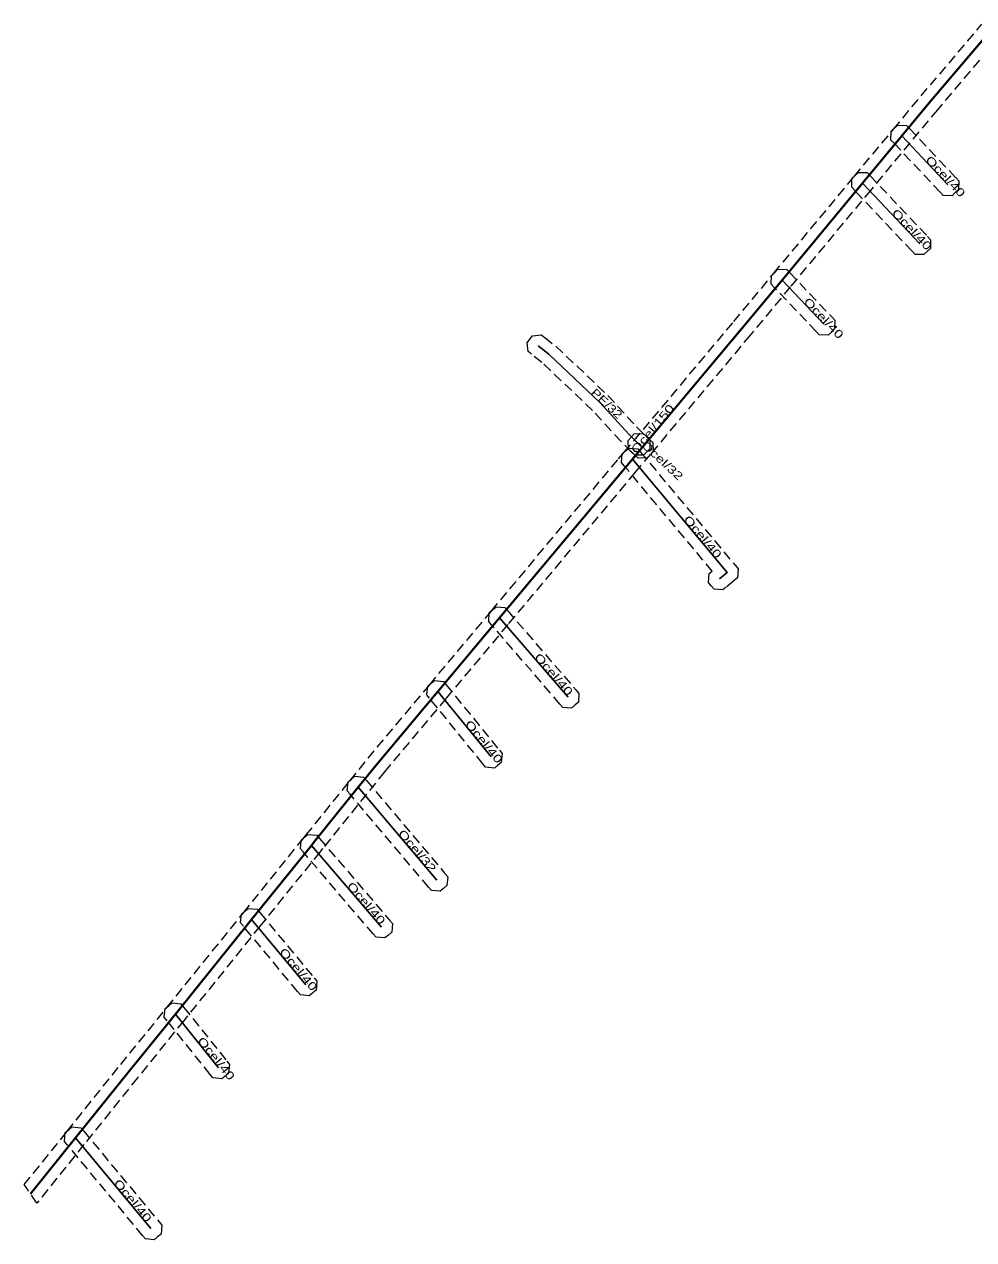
# Model space of a CAD drawing. Extents: x -588392 to -586332, y -1208963 to -1206334.
# Drawn here: x -588392.3 to -588303.3, y -1206538.6 to -1206424.7 of the extents above; entities that cross this region are included whole.
import ezdxf

# ---------------------------------------------------------------- set-up
doc = ezdxf.new("R2010")
doc.units = 0
doc.header["$LTSCALE"] = 0.3
doc.linetypes.add('MEDIUM_DASHED', pattern=[4.5, 3, -1.5])
doc.layers.add('1', color=7, linetype='MEDIUM_DASHED', lineweight=13)
doc.layers.add('24', color=7, linetype='Continuous', lineweight=25)
doc.layers.add('30', color=7, linetype='Continuous')

msp = doc.modelspace()

# ---------------------------------------------------------------- linework, layer by layer
at = {"layer": '1'}
msp.add_lwpolyline([(-588301.028, -1206425.988), (-588306.724, -1206432.693), (-588309.29, -1206435.789), (-588312.971, -1206440.219), (-588320.511, -1206449.299), (-588324.272, -1206453.831), (-588333.617, -1206464.978), (-588334.537, -1206466.076), (-588335.066, -1206466.696), (-588346.983, -1206480.942), (-588352.773, -1206487.852), (-588358.537, -1206494.735), (-588360.215, -1206496.814), (-588364.342, -1206501.928), (-588364.606, -1206502.255), (-588370.212, -1206509.198), (-588377.362, -1206518.059), (-588381.692, -1206523.408), (-588386.721, -1206529.667), (-588391.139, -1206535.159), (-588392.299, -1206533.411), (-588388.279, -1206528.413), (-588383.248, -1206522.152), (-588378.918, -1206516.801), (-588371.768, -1206507.942), (-588366.162, -1206500.999), (-588365.898, -1206500.672), (-588361.771, -1206495.558), (-588360.083, -1206493.465), (-588354.307, -1206486.568), (-588348.517, -1206479.658), (-588336.594, -1206465.404), (-588336.063, -1206464.784), (-588335.149, -1206463.694), (-588325.808, -1206452.549), (-588322.049, -1206448.021), (-588314.509, -1206438.941), (-588310.83, -1206434.511), (-588308.256, -1206431.407), (-588302.552, -1206424.692)], dxfattribs=at)
for points in [[(-588309.617, -1206434.162), (-588309.333, -1206434.464), (-588305.003, -1206439.054), (-588304.718, -1206439.355), (-588304.742, -1206440.183), (-588305.044, -1206440.467), (-588305.345, -1206440.752), (-588306.173, -1206440.728), (-588306.457, -1206440.426), (-588310.787, -1206435.836), (-588311.072, -1206435.535), (-588311.048, -1206434.707), (-588310.746, -1206434.423), (-588310.445, -1206434.138)], [(-588313.298, -1206438.592), (-588313.013, -1206438.893), (-588307.643, -1206444.573), (-588307.358, -1206444.874), (-588307.382, -1206445.702), (-588307.683, -1206445.987), (-588307.984, -1206446.272), (-588308.812, -1206446.248), (-588309.097, -1206445.947), (-588314.467, -1206440.267), (-588314.752, -1206439.966), (-588314.728, -1206439.138), (-588314.427, -1206438.853), (-588314.126, -1206438.568)], [(-588320.84, -1206447.671), (-588320.555, -1206447.972), (-588316.625, -1206452.112), (-588316.34, -1206452.412), (-588316.361, -1206453.24), (-588316.662, -1206453.525), (-588316.962, -1206453.81), (-588317.79, -1206453.789), (-588318.075, -1206453.488), (-588322.005, -1206449.348), (-588322.29, -1206449.048), (-588322.269, -1206448.22), (-588321.968, -1206447.935), (-588321.668, -1206447.65)], [(-588335.094, -1206465.06), (-588335.387, -1206464.767), (-588336.373, -1206463.781), (-588339.034, -1206460.872), (-588343.795, -1206456.367), (-588344.76, -1206455.605), (-588345.085, -1206455.348), (-588345.182, -1206454.525), (-588344.925, -1206454.2), (-588344.668, -1206453.875), (-588343.845, -1206453.778), (-588343.52, -1206454.035), (-588342.485, -1206454.853), (-588337.606, -1206459.468), (-588334.927, -1206462.399), (-588333.973, -1206463.353), (-588333.68, -1206463.646), (-588333.68, -1206464.474), (-588333.973, -1206464.767), (-588334.266, -1206465.06)], [(-588334.76, -1206465.351), (-588335.064, -1206465.069), (-588335.361, -1206464.793), (-588335.664, -1206464.511), (-588335.695, -1206463.683), (-588335.413, -1206463.379), (-588335.131, -1206463.076), (-588334.303, -1206463.045), (-588333.999, -1206463.327), (-588333.702, -1206463.603), (-588333.399, -1206463.885), (-588333.368, -1206464.713), (-588333.65, -1206465.017), (-588333.932, -1206465.32)], [(-588328.109, -1206476.159), (-588327.828, -1206475.924), (-588336.067, -1206466.071), (-588336.333, -1206465.753), (-588336.259, -1206464.929), (-588335.941, -1206464.663), (-588335.623, -1206464.397), (-588334.799, -1206464.471), (-588334.533, -1206464.789), (-588325.653, -1206475.409), (-588325.387, -1206475.726), (-588325.424, -1206476.139), (-588325.461, -1206476.552), (-588325.779, -1206476.817), (-588326.509, -1206477.427), (-588326.827, -1206477.693), (-588327.651, -1206477.619), (-588327.917, -1206477.301), (-588328.183, -1206476.983)], [(-588347.263, -1206479.333), (-588346.993, -1206479.647), (-588340.583, -1206487.077), (-588340.313, -1206487.391), (-588340.373, -1206488.217), (-588340.687, -1206488.487), (-588341.001, -1206488.757), (-588341.827, -1206488.697), (-588342.097, -1206488.383), (-588348.507, -1206480.953), (-588348.777, -1206480.639), (-588348.717, -1206479.813), (-588348.403, -1206479.543), (-588348.089, -1206479.273)], [(-588353.026, -1206486.258), (-588352.764, -1206486.579), (-588347.774, -1206492.709), (-588347.513, -1206493.03), (-588347.598, -1206493.854), (-588347.919, -1206494.116), (-588348.24, -1206494.377), (-588349.064, -1206494.292), (-588349.326, -1206493.971), (-588354.316, -1206487.841), (-588354.577, -1206487.52), (-588354.492, -1206486.696), (-588354.171, -1206486.434), (-588353.85, -1206486.173)], [(-588354.147, -1206505.858), (-588354.414, -1206505.542), (-588361.758, -1206496.831), (-588362.025, -1206496.514), (-588361.954, -1206495.688), (-588361.638, -1206495.421), (-588361.321, -1206495.154), (-588360.495, -1206495.225), (-588360.228, -1206495.541), (-588352.884, -1206504.252), (-588352.617, -1206504.569), (-588352.688, -1206505.395), (-588353.004, -1206505.662), (-588353.321, -1206505.929)], [(-588364.894, -1206500.662), (-588364.625, -1206500.976), (-588358.072, -1206508.625), (-588357.802, -1206508.94), (-588357.866, -1206509.766), (-588358.18, -1206510.035), (-588358.495, -1206510.305), (-588359.321, -1206510.241), (-588359.59, -1206509.927), (-588366.143, -1206502.278), (-588366.413, -1206501.963), (-588366.349, -1206501.137), (-588366.035, -1206500.868), (-588365.72, -1206500.598)], [(-588370.486, -1206507.612), (-588370.221, -1206507.931), (-588365.141, -1206514.041), (-588364.876, -1206514.36), (-588364.952, -1206515.184), (-588365.271, -1206515.449), (-588365.59, -1206515.714), (-588366.414, -1206515.638), (-588366.679, -1206515.319), (-588371.759, -1206509.209), (-588372.024, -1206508.89), (-588371.948, -1206508.066), (-588371.629, -1206507.801), (-588371.31, -1206507.536)], [(-588377.62, -1206516.481), (-588377.36, -1206516.804), (-588373.32, -1206521.834), (-588373.061, -1206522.157), (-588373.151, -1206522.98), (-588373.474, -1206523.24), (-588373.797, -1206523.499), (-588374.62, -1206523.409), (-588374.88, -1206523.086), (-588378.92, -1206518.056), (-588379.179, -1206517.733), (-588379.089, -1206516.91), (-588378.766, -1206516.65), (-588378.443, -1206516.391)], [(-588386.996, -1206528.082), (-588386.731, -1206528.401), (-588379.671, -1206536.901), (-588379.406, -1206537.22), (-588379.482, -1206538.044), (-588379.801, -1206538.309), (-588380.12, -1206538.574), (-588380.944, -1206538.498), (-588381.209, -1206538.179), (-588388.269, -1206529.679), (-588388.534, -1206529.36), (-588388.458, -1206528.536), (-588388.139, -1206528.271), (-588387.82, -1206528.006)]]:
    msp.add_lwpolyline(points, close=True, dxfattribs=at)
at = {"layer": '24'}
for p, q in [((-588310.06, -1206435.15), (-588305.73, -1206439.74)), ((-588313.74, -1206439.58), (-588308.37, -1206445.26)), ((-588321.28, -1206448.66), (-588317.35, -1206452.8)), ((-588334.383, -1206464.336), (-588334.68, -1206464.06)), ((-588347.75, -1206480.3), (-588341.34, -1206487.73)), ((-588353.54, -1206487.21), (-588348.55, -1206493.34)), ((-588353.649, -1206504.897), (-588360.993, -1206496.186)), ((-588365.384, -1206501.627), (-588358.831, -1206509.276)), ((-588370.99, -1206508.57), (-588365.91, -1206514.68)), ((-588378.14, -1206517.43), (-588374.1, -1206522.46)), ((-588387.5, -1206529.04), (-588380.44, -1206537.54))]:
    msp.add_line(p, q, dxfattribs=at)
at = {"layer": '24', "lineweight": 40}
msp.add_lwpolyline([(-588301.79, -1206425.34), (-588307.49, -1206432.05), (-588310.06, -1206435.15), (-588313.74, -1206439.58), (-588321.28, -1206448.66), (-588325.04, -1206453.19), (-588334.383, -1206464.336), (-588335.3, -1206465.43), (-588335.83, -1206466.05), (-588347.75, -1206480.3), (-588353.54, -1206487.21), (-588359.31, -1206494.1), (-588360.993, -1206496.186), (-588365.12, -1206501.3), (-588365.384, -1206501.627), (-588370.99, -1206508.57), (-588378.14, -1206517.43), (-588382.47, -1206522.78), (-588387.5, -1206529.04), (-588391.719, -1206534.285)], dxfattribs=at)
at = {"layer": '24'}
for points in [[(-588334.68, -1206464.06), (-588335.65, -1206463.09), (-588338.32, -1206460.17), (-588343.14, -1206455.61), (-588344.14, -1206454.82)], [(-588327.15, -1206476.66), (-588326.42, -1206476.05), (-588335.3, -1206465.43)]]:
    msp.add_lwpolyline(points, dxfattribs=at)

# ---------------------------------------------------------------- texts
at = {"layer": '30'}
for s, rotation, width, p in [('Ocel/40', 313.33, 1.4, (-588307.895, -1206437.445)), ('Ocel/40', 313.393, 1.4, (-588311.055, -1206442.42)), ('Ocel/40', 313.509, 1.4, (-588319.315, -1206450.73)), ('PE/32', 316.588, 1.3, (-588339.257, -1206459.283)), ('Ocel/150', 50.03, 1.4, (-588334.938, -1206464.998)), ('Ocel/32', 317.099, 1.4, (-588334.531, -1206464.198)), ('Ocel/40', 309.901, 1.4, (-588330.555, -1206471.105)), ('Ocel/40', 310.785, 1.4, (-588344.545, -1206484.015)), ('Ocel/40', 309.147, 1.4, (-588351.045, -1206490.275)), ('Ocel/32', 310.133, 1.4, (-588357.321, -1206500.541)), ('Ocel/40', 310.587, 1.4, (-588362.107, -1206505.451)), ('Ocel/40', 309.741, 1.4, (-588368.45, -1206511.625)), ('Ocel/40', 308.771, 1.4, (-588376.12, -1206519.945)), ('Ocel/40', 309.713, 1.4, (-588383.97, -1206533.29))]:
    msp.add_text(s, height=0.75, rotation=rotation, dxfattribs=dict(at, width=width)).set_placement(p)

doc.saveas('drawing.dxf')
